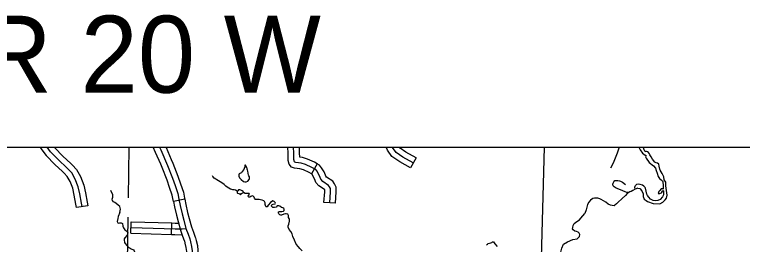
# Model space of a CAD drawing. Extents: x 813775 to 1157140, y 1757555 to 1979907.
# Drawn here: x 951173 to 970084, y 1878184 to 1884157 of the extents above; entities that cross this region are included whole.
import ezdxf

# ---------------------------------------------------------------- set-up
doc = ezdxf.new("R2010")
doc.units = 0
for name, color, linetype in [('Level 31', 7, 'Continuous'), ('Level 32', 7, 'Continuous'), ('Level 35', 7, 'Continuous'), ('Level 5', 7, 'Continuous'), ('Level 7', 7, 'Continuous'), ('Level 9', 7, 'Continuous'), ('R_Draft', 7, 'Continuous')]:
    doc.layers.add(name, color=color, linetype=linetype)

msp = doc.modelspace()

# ---------------------------------------------------------------- linework, layer by layer
at = {"layer": 'Level 31'}
for p, q in [((955595, 1879360), (955301, 1879301)), ((953075, 1879189), (952778, 1879145))]:
    msp.add_line(p, q, dxfattribs=at)
for points in [[(951840, 1880709), (951857, 1880673), (951997, 1880492), (952219, 1880265), (952419, 1880079), (952459, 1880036)], [(952926, 1879167), (952913, 1879256), (952868, 1879497), (952828, 1879685), (952752, 1879881), (952659, 1880042), (952525, 1880185), (952324, 1880372), (952110, 1880591), (952018, 1880709)], [(952678, 1880241), (952631, 1880291), (952429, 1880480), (952223, 1880690), (952208, 1880709)], [(954970, 1880267), (954835, 1880575), (954771, 1880709)], [(954938, 1880709), (954972, 1880638), (955148, 1880236), (955277, 1879908), (955344, 1879714), (955413, 1879506), (955442, 1879361), (955476, 1879194), (955525, 1878977), (955567, 1878816), (955625, 1878599), (955681, 1878453)], [(955104, 1880709), (955108, 1880700), (955245, 1880388)], [(959333, 1879718), (959179, 1879820), (959130, 1879876), (959110, 1879925), (959079, 1880001), (959027, 1880093), (958998, 1880128), (958896, 1880186), (958735, 1880262), (958619, 1880294), (958483, 1880314), (958454, 1880323), (958445, 1880334), (958432, 1880387), (958428, 1880559), (958424, 1880709)], [(955245, 1880388), (955286, 1880294), (955418, 1879960), (955486, 1879762), (955558, 1879545), (955589, 1879390), (955595, 1879360)], [(952678, 1880241), (952780, 1880132), (952888, 1879947), (952972, 1879728), (953015, 1879527), (953061, 1879281), (953075, 1879189)], [(955301, 1879301), (955295, 1879332), (955268, 1879468), (955202, 1879666), (955136, 1879856), (955009, 1880179), (954970, 1880267)], [(952778, 1879145), (952765, 1879232), (952721, 1879468), (952684, 1879642), (952617, 1879816), (952538, 1879952), (952459, 1880036)], [(959362, 1879266), (959382, 1879550), (959378, 1879636), (959357, 1879682), (959333, 1879718)], [(955301, 1879301), (955329, 1879162), (955379, 1878941), (955422, 1878778), (955482, 1878553), (955540, 1878401), (955580, 1878287), (955584, 1878274)], [(955595, 1879360), (955622, 1879225), (955670, 1879013), (955712, 1878855), (955768, 1878645), (955822, 1878505), (955866, 1878377), (955873, 1878354)], [(955584, 1878274), (955600, 1878215), (955627, 1878102), (955640, 1878002), (955648, 1877855), (955650, 1877680), (955638, 1877322), (955637, 1877267)], [(955681, 1878453), (955723, 1878332), (955745, 1878252), (955774, 1878129), (955790, 1878015), (955797, 1877859), (955800, 1877678), (955788, 1877318)], [(955873, 1878354), (955891, 1878289), (955922, 1878157), (955939, 1878029), (955947, 1877864), (955950, 1877677), (955938, 1877314), (955937, 1877263)]]:
    msp.add_lwpolyline(points, dxfattribs=at)
at = {"layer": 'Level 32'}
for p, q in [((961605, 1880436), (961460, 1880173)), ((959032, 1880282), (958884, 1880021)), ((959511, 1879256), (959212, 1879277)), ((954197, 1878474), (954206, 1878774)), ((955252, 1878443), (955261, 1878743))]:
    msp.add_line(p, q, dxfattribs=at)
for points in [[(958884, 1880021), (958827, 1880053), (958683, 1880121), (958589, 1880146), (958450, 1880167), (958366, 1880193), (958308, 1880266), (958283, 1880367), (958278, 1880555), (958274, 1880709)], [(959032, 1880282), (958965, 1880320), (958787, 1880404), (958650, 1880441), (958581, 1880451), (958578, 1880563), (958574, 1880709)], [(961460, 1880173), (961180, 1880327), (960978, 1880466), (960865, 1880630), (960825, 1880709)], [(961533, 1880304), (961259, 1880455), (961086, 1880574), (960994, 1880706), (960993, 1880709)], [(961605, 1880436), (961338, 1880583), (961193, 1880682), (961175, 1880709)], [(959511, 1879256), (959533, 1879548), (959526, 1879672), (959489, 1879756), (959440, 1879826), (959279, 1879934), (959259, 1879956), (959249, 1879982), (959214, 1880067), (959152, 1880177), (959097, 1880245), (959032, 1880282)], [(959212, 1879277), (959232, 1879551), (959230, 1879601), (959226, 1879608), (959226, 1879609), (959079, 1879707), (959001, 1879796), (958971, 1879868), (958943, 1879936), (958903, 1880008), (958900, 1880012), (958884, 1880021)], [(954206, 1878774), (955261, 1878743)], [(955261, 1878743), (955345, 1878740), (955432, 1878739)], [(954197, 1878474), (955252, 1878443)], [(954201, 1878624), (955342, 1878590), (955529, 1878588), (955625, 1878599)], [(955252, 1878443), (955339, 1878440), (955527, 1878438)]]:
    msp.add_lwpolyline(points, dxfattribs=at)
at = {"layer": 'Level 35'}
for points in [[(966879, 1880709), (966829, 1880556), (966728, 1880300), (966655, 1880164)], [(957151, 1880185), (957129, 1880135), (957087, 1880075), (957070, 1880048), (957043, 1880037), (957011, 1880022), (956998, 1879997), (956997, 1879959), (957020, 1879916), (957060, 1879869), (957119, 1879819), (957153, 1879812), (957193, 1879812), (957237, 1879831), (957267, 1879872), (957279, 1879890), (957279, 1879923), (957277, 1879943), (957258, 1879968), (957254, 1879985), (957246, 1880037), (957234, 1880090), (957221, 1880120), (957219, 1880135), (957217, 1880156), (957212, 1880177), (957199, 1880203), (957183, 1880224), (957169, 1880240), (957157, 1880241), (957153, 1880238), (957152, 1880186)], [(956955, 1879570), (956915, 1879594), (956881, 1879599), (956848, 1879603), (956816, 1879609), (956783, 1879622), (956741, 1879646), (956698, 1879676), (956662, 1879701), (956617, 1879742), (956560, 1879786), (956470, 1879836), (956357, 1879903), (956327, 1879946), (956319, 1879970)], [(967132, 1879537), (967083, 1879536), (967038, 1879548), (966913, 1879599), (966801, 1879647), (966748, 1879681), (966722, 1879708), (966718, 1879729), (966714, 1879749), (966722, 1879775), (966740, 1879811), (966767, 1879843), (966806, 1879847), (966845, 1879844), (966889, 1879840), (966915, 1879824), (966967, 1879798), (967046, 1879741)], [(957120, 1879533), (957114, 1879560), (957083, 1879581), (957049, 1879591), (957028, 1879601), (957013, 1879601), (956992, 1879601), (956971, 1879581), (956955, 1879570), (956953, 1879521), (956963, 1879513), (956997, 1879505), (957018, 1879510), (957026, 1879492), (957041, 1879481), (957054, 1879481), (957070, 1879505), (957083, 1879515), (957120, 1879533)], [(967297, 1879624), (967239, 1879586), (967196, 1879560), (967160, 1879550), (967132, 1879537), (967093, 1879506), (967044, 1879460), (966963, 1879381), (966851, 1879276), (966812, 1879240), (966769, 1879201), (966753, 1879190), (966701, 1879193), (966654, 1879203), (966594, 1879229), (966531, 1879280), (966471, 1879321), (966413, 1879352), (966375, 1879372), (966330, 1879385), (966293, 1879389), (966243, 1879390), (966196, 1879375), (966140, 1879331), (966094, 1879284), (966058, 1879225)], [(953910, 1879012), (953923, 1879103), (953907, 1879166), (953868, 1879205), (953813, 1879246), (953774, 1879270), (953746, 1879293), (953719, 1879327), (953712, 1879359), (953722, 1879411), (953727, 1879448), (953722, 1879476), (953675, 1879583)], [(958292, 1878883), (958287, 1878939), (958272, 1878968), (958232, 1878981), (958209, 1878981), (958165, 1878971), (958112, 1878945), (958094, 1878945), (958063, 1878955), (958039, 1878979), (958032, 1878999), (958034, 1879031), (958060, 1879039), (958115, 1879036), (958159, 1879046), (958178, 1879070), (958178, 1879099), (958167, 1879120), (958139, 1879135), (958110, 1879148), (958065, 1879180), (958037, 1879190), (957998, 1879190), (957972, 1879151), (957930, 1879140), (957886, 1879146), (957852, 1879177), (957852, 1879195), (957859, 1879211), (957893, 1879232), (957943, 1879237), (957953, 1879255), (957946, 1879274), (957919, 1879302), (957886, 1879315), (957820, 1879276), (957766, 1879203), (957732, 1879164), (957708, 1879161), (957698, 1879167), (957687, 1879221), (957688, 1879267), (957669, 1879296), (957646, 1879314), (957604, 1879338), (957560, 1879346), (957526, 1879348), (957484, 1879348), (957437, 1879356), (957424, 1879364), (957411, 1879385), (957401, 1879416), (957380, 1879434), (957362, 1879445), (957333, 1879437), (957312, 1879427), (957286, 1879411), (957262, 1879416), (957247, 1879424), (957244, 1879440), (957260, 1879468), (957273, 1879492), (957265, 1879507), (957239, 1879510), (957215, 1879510), (957197, 1879505), (957166, 1879507), (957120, 1879533)], [(966058, 1879225), (966020, 1879085), (965986, 1878986)], [(953910, 1879012), (953863, 1878912), (953852, 1878858), (953842, 1878779), (953858, 1878742)], [(958645, 1878018), (958582, 1878076), (958548, 1878123), (958493, 1878193), (958444, 1878293), (958399, 1878387), (958384, 1878457), (958350, 1878520), (958311, 1878575), (958282, 1878629), (958282, 1878671), (958300, 1878715), (958316, 1878791), (958313, 1878830), (958305, 1878856), (958292, 1878883)], [(965405, 1877775), (965353, 1877862), (965361, 1877945), (965390, 1878084), (965432, 1878193), (965536, 1878256), (965679, 1878311), (965791, 1878334), (965851, 1878387), (965859, 1878439), (965844, 1878481), (965815, 1878507), (965773, 1878522), (965732, 1878533), (965682, 1878564), (965672, 1878588), (965677, 1878624), (965685, 1878679), (965713, 1878726), (965781, 1878778), (965848, 1878824), (965888, 1878867), (965986, 1878986)], [(953858, 1878742), (953881, 1878734), (953912, 1878749), (953944, 1878747), (953978, 1878726), (953988, 1878661), (954001, 1878614), (954038, 1878567), (954092, 1878528), (954113, 1878483), (954098, 1878423), (954035, 1878353), (954022, 1878327), (954017, 1878306)], [(954017, 1878306), (954027, 1878239), (954045, 1878207), (954087, 1878160), (954121, 1878116), (954176, 1878085), (954205, 1878069), (954259, 1878048), (954283, 1878019), (954288, 1877988), (954280, 1877946), (954252, 1877910), (954168, 1877842)], [(963436, 1878173), (963460, 1878191), (963481, 1878212), (963515, 1878217), (963543, 1878222), (963572, 1878238), (963587, 1878253), (963611, 1878256), (963618, 1878251), (963652, 1878204), (963715, 1878128)]]:
    msp.add_lwpolyline(points, dxfattribs=at)
at = {"layer": 'Level 5'}
for points in [[(954141, 1880709), (954123, 1879394)], [(954116, 1878890), (954075, 1875927)]]:
    msp.add_lwpolyline(points, dxfattribs=at)
at = {"layer": 'Level 7'}
msp.add_lwpolyline([(964937, 1880709), (964847, 1877516), (964156, 1876451), (963498, 1876461), (963485, 1875786), (962535, 1875798), (962497, 1873113), (963168, 1873116)], dxfattribs=at)
at = {"layer": 'Level 9'}
for points in [[(967368, 1879645), (967418, 1879640), (967470, 1879578), (967507, 1879502), (967509, 1879431), (967530, 1879361), (967585, 1879324), (967621, 1879303), (967767, 1879251), (967937, 1879241), (968013, 1879285), (968073, 1879343), (968109, 1879390), (968125, 1879468), (968114, 1879588), (968096, 1879706), (968091, 1879802), (968054, 1879862), (968044, 1879938), (968002, 1880027), (967950, 1880110), (967940, 1880144), (967924, 1880222), (967908, 1880272), (967880, 1880298), (967840, 1880306), (967804, 1880324), (967749, 1880397), (967710, 1880456), (967679, 1880511), (967671, 1880537), (967642, 1880574), (967614, 1880592), (967595, 1880602)], [(967389, 1880709), (967431, 1880646), (967491, 1880558), (967559, 1880505), (967577, 1880500)], [(967509, 1880709), (967509, 1880704), (967525, 1880652), (967541, 1880620)], [(967541, 1880620), (967554, 1880607), (967571, 1880602)], [(967595, 1880602), (967571, 1880602)], [(967577, 1880500), (967574, 1880482), (967569, 1880461), (967582, 1880427), (967663, 1880317), (967775, 1880229), (967822, 1880166), (967840, 1880103), (967869, 1880035), (967898, 1879946), (967932, 1879899), (967976, 1879865), (968013, 1879818), (968023, 1879706), (968026, 1879635), (968023, 1879622), (968005, 1879630), (967971, 1879630), (967937, 1879585), (967911, 1879562), (967895, 1879512), (967906, 1879504), (967937, 1879512), (967979, 1879523), (968005, 1879567), (968028, 1879585), (968036, 1879578), (968031, 1879473), (968010, 1879418), (967950, 1879348), (967887, 1879327), (967830, 1879319), (967765, 1879324), (967697, 1879364), (967655, 1879411), (967616, 1879458), (967601, 1879491), (967582, 1879565), (967564, 1879648), (967554, 1879666), (967525, 1879695), (967488, 1879726), (967431, 1879745), (967381, 1879747), (967329, 1879738)], [(967368, 1879645), (967297, 1879624), (967289, 1879671), (967295, 1879696), (967306, 1879713), (967329, 1879738)]]:
    msp.add_lwpolyline(points, dxfattribs=at)
at = {"layer": 'R_Draft'}
msp.add_lwpolyline([(912532, 1880709), (1062535, 1880709), (1062535, 1798155), (912532, 1798155)], close=True, dxfattribs=at)

# ---------------------------------------------------------------- texts
msp.add_text('R 20 W', height=2000, dxfattribs=at).set_placement((950215, 1882127))

doc.saveas('drawing.dxf')
